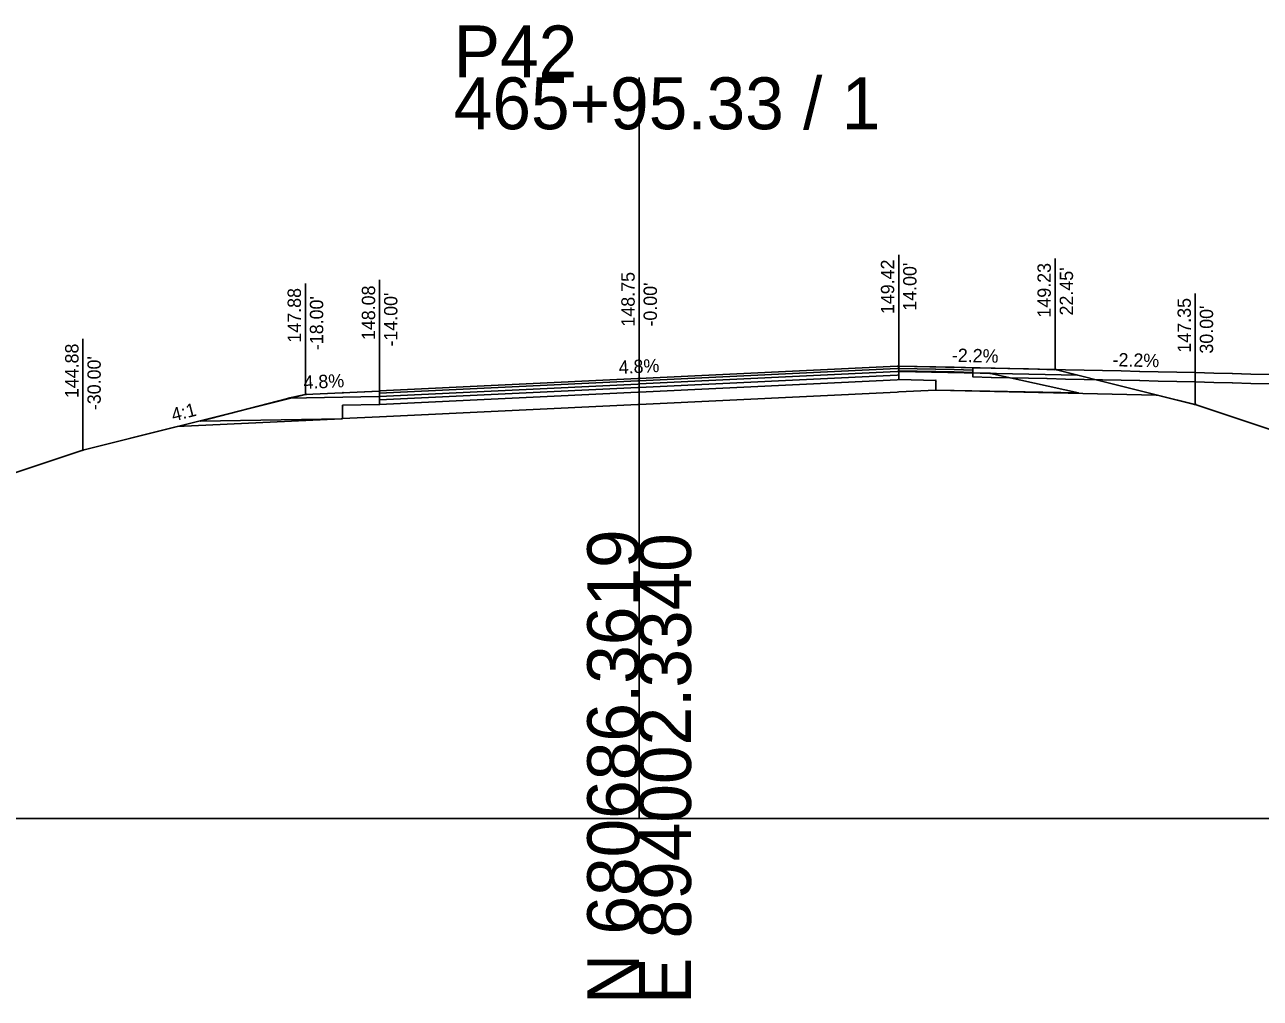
# Model space of a CAD drawing. Extents: x -26 to 4403, y -13 to 9578.
# Drawn here: x 1216.9 to 1283.5, y 7490.3 to 7542.8 of the extents above; entities that cross this region are included whole.
import ezdxf

# ---------------------------------------------------------------- set-up
doc = ezdxf.new("R2010")
doc.units = 0
for name, color, linetype in [('_CIVIL_CONSTRUCTION', 7, 'Continuous'), ('ASPHALT_19MM1', 7, 'Continuous'), ('ASPHALT_19MM2', 7, 'Continuous'), ('ASPHALT_9_5MM1', 7, 'Continuous'), ('CONST_LV3', 7, 'Continuous'), ('Default', 7, 'Continuous'), ('DTM_P_FINISHED_GRADE', 7, 'Continuous'), ('DTM_TEMP_DROP', 7, 'Continuous'), ('SLOPE_STAKES_FILL', 7, 'Continuous'), ('XS_CELL', 7, 'Continuous'), ('XS_P_ASPHALT', 7, 'Continuous'), ('XS_P_CRUSHED_STONE', 7, 'Continuous'), ('XS_P_DR_ASPHALT', 7, 'Continuous'), ('XS_P_DR_ASPHALT_B', 7, 'Continuous'), ('XS_P_DR_GRAVEL', 7, 'Continuous'), ('XS_P_GROUND', 7, 'Continuous'), ('XS_P_SHOULDER', 7, 'Continuous'), ('XS_P_SUBGRADE_GRANULAR', 7, 'Continuous'), ('XS_P_TX_CLEARZONE', 7, 'Continuous'), ('XS_P_TX_FS_BS', 7, 'Continuous')]:
    doc.layers.add(name, color=color, linetype=linetype)

msp = doc.modelspace()

# ---------------------------------------------------------------- linework, layer by layer
at = {"layer": 'ASPHALT_19MM1'}
for points in [[(1263.924, 7524.125), (1250, 7523.457), (1250, 7523.456), (1250, 7523.27), (1263.924, 7523.937), (1264, 7523.941), (1264, 7524.128), (1264, 7524.129), (1263.924, 7524.125)], [(1249.924, 7523.453), (1236, 7522.785), (1236, 7522.784), (1236, 7522.597), (1249.924, 7523.266), (1250, 7523.27), (1250, 7523.456), (1250, 7523.457), (1249.924, 7523.453)]]:
    msp.add_lwpolyline(points, dxfattribs=at)
at = {"layer": 'ASPHALT_19MM2'}
for points in [[(1263.924, 7523.937), (1250, 7523.27), (1250, 7523.268), (1250, 7523.02), (1263.924, 7523.687), (1264, 7523.691), (1264, 7523.94), (1264, 7523.941), (1263.924, 7523.937)], [(1249.924, 7523.266), (1236, 7522.597), (1236, 7522.596), (1236, 7522.347), (1249.924, 7523.016), (1250, 7523.02), (1250, 7523.268), (1250, 7523.27), (1249.924, 7523.266)]]:
    msp.add_lwpolyline(points, dxfattribs=at)
at = {"layer": 'ASPHALT_9_5MM1'}
for points in [[(1263.924, 7524.417), (1250, 7523.749), (1250, 7523.748), (1250, 7523.624), (1263.924, 7524.292), (1264, 7524.296), (1264, 7524.42), (1264, 7524.421), (1263.924, 7524.417)], [(1249.924, 7523.745), (1236, 7523.077), (1236, 7523.076), (1236, 7522.951), (1249.924, 7523.62), (1250, 7523.624), (1250, 7523.748), (1250, 7523.749), (1249.924, 7523.745)]]:
    msp.add_lwpolyline(points, dxfattribs=at)
at = {"layer": 'CONST_LV3'}
for points in [[(1264, 7524.421), (1264.996, 7524.399), (1265.996, 7524.377), (1266.996, 7524.355), (1267.996, 7524.333), (1268.996, 7524.311), (1269.996, 7524.289), (1270.996, 7524.267), (1271.996, 7524.245), (1272.996, 7524.223), (1273.996, 7524.201), (1274.996, 7524.179), (1275.996, 7524.157), (1276.996, 7524.135), (1277.996, 7524.113), (1278.996, 7524.091), (1279.996, 7524.069), (1280, 7524.069), (1280.996, 7524.042), (1281.996, 7524.016), (1282.996, 7523.989), (1283.996, 7523.963)], [(1280, 7522.346), (1279.991, 7522.349), (1277.959, 7522.857)], [(1225.084, 7521.156), (1220, 7519.885)]]:
    msp.add_lwpolyline(points, dxfattribs=at)
at = {"layer": 'Default'}
for points in [[(1263.924, 7524.292), (1250, 7523.624), (1250, 7523.623), (1250, 7523.457), (1263.924, 7524.125), (1264, 7524.129), (1264, 7524.295), (1264, 7524.296), (1263.924, 7524.292)], [(1249.924, 7523.62), (1236, 7522.951), (1236, 7522.951), (1236, 7522.785), (1249.924, 7523.453), (1250, 7523.457), (1250, 7523.623), (1250, 7523.624), (1249.924, 7523.62)]]:
    msp.add_lwpolyline(points, dxfattribs=at)
at = {"layer": 'DTM_P_FINISHED_GRADE'}
for points in [[(1264, 7524.421), (1264.996, 7524.399), (1265, 7524.399), (1265.996, 7524.377), (1266, 7524.377), (1266.996, 7524.355), (1267, 7524.355), (1267.996, 7524.333), (1268, 7524.333)], [(1268, 7524.333), (1268, 7524.333), (1268.996, 7524.311), (1269, 7524.311), (1269.996, 7524.289), (1270, 7524.289), (1270.996, 7524.267), (1271, 7524.267), (1271.996, 7524.245), (1272, 7524.245), (1272.996, 7524.223), (1273, 7524.223), (1273.996, 7524.201), (1274, 7524.201), (1274.996, 7524.179), (1275, 7524.179), (1275.996, 7524.157), (1276, 7524.157), (1276.996, 7524.135), (1277, 7524.135), (1277.996, 7524.113), (1278, 7524.113), (1278.996, 7524.091), (1279, 7524.091), (1279.996, 7524.069), (1280, 7524.069), (1280.996, 7524.042), (1281, 7524.042), (1281.996, 7524.016), (1282, 7524.016), (1282.996, 7523.989), (1283, 7523.989), (1283.996, 7523.963)]]:
    msp.add_lwpolyline(points, dxfattribs=at)
at = {"layer": 'XS_CELL'}
for p, q in [((1250, 7500), (1250, 7540)), ((1000, 7500), (1250, 7500)), ((1250, 7500), (1400, 7500))]:
    msp.add_line(p, q, dxfattribs=at)
at = {"layer": 'XS_P_ASPHALT'}
msp.add_lwpolyline([(1249.924, 7523.745), (1236, 7523.077), (1236, 7523.073), (1236, 7522.347), (1249.924, 7523.016), (1250, 7523.02), (1263.924, 7523.688), (1264, 7523.692), (1264, 7524.417), (1264, 7524.421), (1263.924, 7524.417), (1250, 7523.749), (1249.924, 7523.745)], dxfattribs=at)
at = {"layer": 'XS_P_CRUSHED_STONE'}
for p, q in [((1264.011, 7524.42), (1264, 7524.421)), ((1264, 7524.421), (1264, 7524.419)), ((1264, 7524.419), (1264, 7524.129)), ((1266, 7524.377), (1264.011, 7524.42)), ((1272.409, 7524.236), (1266, 7524.377)), ((1264, 7524.129), (1264.027, 7524.128)), ((1264.027, 7524.128), (1273.644, 7523.935)), ((1272.446, 7524.235), (1272.409, 7524.236)), ((1272.425, 7524.234), (1272.446, 7524.235)), ((1273.644, 7523.935), (1272.446, 7524.235))]:
    msp.add_line(p, q, dxfattribs=at)
for points in [[(1265.989, 7523.119), (1266, 7523.12), (1265.995, 7523.646), (1265.995, 7523.648), (1264.011, 7523.691), (1264, 7523.691), (1263.924, 7523.687), (1250, 7523.02), (1250, 7523.016), (1250, 7522.353), (1263.924, 7523.02), (1264, 7523.024), (1265.989, 7523.119)], [(1233.989, 7522.98), (1232, 7522.885), (1231.995, 7522.884), (1231.078, 7522.686), (1235.973, 7522.784), (1236, 7522.785), (1236, 7523.075), (1236, 7523.077), (1235.989, 7523.076), (1234, 7522.981), (1233.989, 7522.98)], [(1235.989, 7521.679), (1234, 7521.584), (1234.005, 7522.301), (1234.005, 7522.305), (1235.989, 7522.347), (1236, 7522.347), (1249.924, 7523.016), (1250, 7523.02), (1250, 7523.016), (1250, 7522.353), (1249.924, 7522.349), (1236, 7521.68), (1235.989, 7521.679)]]:
    msp.add_lwpolyline(points, dxfattribs=at)
at = {"layer": 'XS_P_DR_ASPHALT'}
msp.add_lwpolyline([(1264, 7524.421), (1264, 7524.296), (1264.996, 7524.274), (1264.996, 7524.274), (1265, 7524.274), (1265.996, 7524.252), (1265.996, 7524.252), (1266, 7524.252), (1266, 7524.252), (1266, 7524.252), (1266.996, 7524.23), (1267, 7524.23), (1267.996, 7524.208), (1268, 7524.208), (1268, 7524.333), (1267.996, 7524.333), (1267, 7524.355), (1266.996, 7524.355), (1266, 7524.377), (1266, 7524.377), (1266, 7524.377), (1265.996, 7524.377), (1265.996, 7524.377), (1265, 7524.399), (1264.996, 7524.399), (1264.996, 7524.399), (1264, 7524.421)], dxfattribs=at)
at = {"layer": 'XS_P_DR_ASPHALT_B'}
msp.add_lwpolyline([(1264, 7524.296), (1264, 7524.171), (1264.996, 7524.149), (1264.996, 7524.149), (1265, 7524.149), (1265.996, 7524.127), (1265.996, 7524.127), (1266, 7524.127), (1266, 7524.127), (1266, 7524.127), (1266.996, 7524.105), (1267, 7524.105), (1267.996, 7524.083), (1268, 7524.083), (1268, 7524.208), (1267.996, 7524.208), (1267, 7524.23), (1266.996, 7524.23), (1266, 7524.252), (1266, 7524.252), (1266, 7524.252), (1265.996, 7524.252), (1265.996, 7524.252), (1265, 7524.274), (1264.996, 7524.274), (1264.996, 7524.274), (1264, 7524.296)], dxfattribs=at)
at = {"layer": 'XS_P_DR_GRAVEL'}
for points in [[(1268, 7524.333), (1268, 7523.833), (1268.996, 7523.811), (1269, 7523.811), (1269.996, 7523.789), (1269.996, 7523.789), (1270, 7523.789), (1270.996, 7523.767), (1271, 7523.767), (1271.996, 7523.745), (1272, 7523.745), (1272, 7523.745), (1272.996, 7523.723), (1273, 7523.723), (1273.996, 7523.701), (1274, 7523.701), (1274.996, 7523.679), (1275, 7523.679), (1275.996, 7523.657), (1276, 7523.657), (1276.996, 7523.635), (1277, 7523.635), (1277.996, 7523.613), (1278, 7523.613), (1278.996, 7523.591), (1279, 7523.591), (1279.996, 7523.569), (1280, 7523.569), (1280.996, 7523.542), (1281, 7523.542), (1281.996, 7523.516), (1282, 7523.516), (1282.996, 7523.489), (1283, 7523.489), (1283.996, 7523.463)], [(1283.996, 7523.963), (1283, 7523.989), (1282.996, 7523.989), (1282, 7524.016), (1281.996, 7524.016), (1281, 7524.042), (1280.996, 7524.042), (1280, 7524.069), (1279.996, 7524.069), (1279, 7524.091), (1278.996, 7524.091), (1278, 7524.113), (1277.996, 7524.113), (1277, 7524.135), (1276.996, 7524.135), (1276, 7524.157), (1275.996, 7524.157), (1275, 7524.179), (1274.996, 7524.179), (1274, 7524.201), (1273.996, 7524.201), (1273, 7524.223), (1272.996, 7524.223), (1272, 7524.245), (1272, 7524.245), (1271.996, 7524.245), (1271, 7524.267), (1270.996, 7524.267), (1270, 7524.289), (1269.996, 7524.289), (1269.996, 7524.289), (1269, 7524.311), (1268.996, 7524.311), (1268, 7524.333)]]:
    msp.add_lwpolyline(points, dxfattribs=at)
at = {"layer": 'XS_P_GROUND'}
for points in [[(1302.257, 7514.928), (1302.134, 7514.969), (1280, 7522.346), (1279.961, 7522.356), (1272.446, 7524.235)], [(1232, 7522.885), (1220, 7519.885), (1199.755, 7513.137), (1195.278, 7511.645), (1190.765, 7510.141)]]:
    msp.add_lwpolyline(points, dxfattribs=at)
at = {"layer": 'XS_P_SHOULDER'}
for points in [[(1272.446, 7524.235), (1272.398, 7524.236), (1264, 7524.421)], [(1232, 7522.885), (1235.978, 7523.076), (1236, 7523.077)]]:
    msp.add_lwpolyline(points, dxfattribs=at)
at = {"layer": 'XS_P_SUBGRADE_GRANULAR'}
for points in [[(1264, 7524.126), (1264, 7523.691), (1264.011, 7523.691), (1265.995, 7523.648), (1265.995, 7523.646), (1266, 7523.12), (1266.042, 7523.119), (1273.703, 7522.97), (1268.947, 7524.024), (1268.922, 7524.03), (1264.027, 7524.128), (1264, 7524.129), (1264, 7524.126)], [(1264, 7523.024), (1263.924, 7523.02), (1250, 7522.353)], [(1277.959, 7522.857), (1277.892, 7522.858), (1266, 7523.12), (1265.989, 7523.119), (1264, 7523.024)], [(1236, 7522.782), (1236, 7522.785), (1235.973, 7522.784), (1231.078, 7522.686), (1231.053, 7522.679), (1226.327, 7521.441), (1233.958, 7521.583), (1234, 7521.584), (1234.005, 7522.301), (1234.005, 7522.305), (1235.989, 7522.347), (1236, 7522.347), (1236, 7522.782)], [(1236, 7521.68), (1249.924, 7522.349), (1250, 7522.353)], [(1225.084, 7521.156), (1233.951, 7521.581), (1234, 7521.584), (1235.989, 7521.679), (1236, 7521.68)]]:
    msp.add_lwpolyline(points, dxfattribs=at)
at = {"layer": 'XS_P_TX_CLEARZONE'}
for p, q in [((1264, 7524.421), (1264, 7530.421)), ((1250, 7523.749), (1250, 7529.749)), ((1272.446, 7524.235), (1272.446, 7530.235)), ((1236, 7523.077), (1236, 7529.077)), ((1232, 7522.885), (1232, 7528.885)), ((1280, 7522.346), (1280, 7528.346)), ((1220, 7519.885), (1220, 7525.885))]:
    msp.add_line(p, q, dxfattribs=at)

# ---------------------------------------------------------------- texts
at = {"layer": '_CIVIL_CONSTRUCTION'}
for p in [(1263.961, 7524.361), (1249.961, 7523.689), (1265.956, 7523.588), (1268.882, 7523.97), (1233.961, 7522.921), (1235.961, 7523.017), (1231.039, 7522.626), (1233.966, 7522.245)]:
    msp.add_text('X', height=0.12, dxfattribs=at).set_placement(p)
at = {"layer": 'DTM_TEMP_DROP'}
for p in [(1272.406, 7524.175), (1231.961, 7522.825)]:
    msp.add_text('X', height=0.12, dxfattribs=at).set_placement(p)
at = {"layer": 'SLOPE_STAKES_FILL'}
for p in [(1279.961, 7522.286), (1219.961, 7519.825)]:
    msp.add_text('X', height=0.12, dxfattribs=at).set_placement(p)
at = {"layer": 'XS_CELL'}
for s, p in [('P42', (1240, 7540)), ('465+95.33 / 1', (1240, 7537.2))]:
    msp.add_text(s, height=2.8, dxfattribs=at).set_placement(p)
for s, p in [('N 680686.3619', (1250, 7490)), ('E 894002.3340', (1252.8, 7490))]:
    msp.add_text(s, height=2.8, rotation=90, dxfattribs=at).set_placement(p)
at = {"layer": 'XS_P_TX_CLEARZONE'}
for s, p in [('149.42', (1263.76, 7527.225)), ("14.00'", (1264.96, 7527.406)), ('149.23', (1272.206, 7527.039)), ("22.45'", (1273.406, 7527.152)), ('148.75', (1249.76, 7526.553)), ('147.88', (1231.76, 7525.689)), ('148.08', (1235.76, 7525.824)), ("-14.00'", (1236.96, 7525.473)), ("-0.00'", (1250.96, 7526.553)), ("-18.00'", (1232.96, 7525.281)), ('147.35', (1279.76, 7525.15)), ("30.00'", (1280.96, 7525.094)), ('144.88', (1219.76, 7522.689)), ("-30.00'", (1220.96, 7522.043))]:
    msp.add_text(s, height=0.72, rotation=90, dxfattribs=at).set_placement(p)
at = {"layer": 'XS_P_TX_FS_BS'}
for s, rotation, p in [('-2.2%', 358.7397, (1266.861, 7524.654)), ('-2.2%', 358.7397, (1275.531, 7524.412)), ('4.8%', 2.74809, (1248.913, 7523.997)), ('4.8%', 2.74809, (1231.913, 7523.181)), ('4:1', 14.19055, (1224.872, 7521.426))]:
    msp.add_text(s, height=0.72, rotation=rotation, dxfattribs=at).set_placement(p)

doc.saveas('drawing.dxf')
